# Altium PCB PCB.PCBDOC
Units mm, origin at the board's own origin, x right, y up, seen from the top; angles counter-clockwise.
Board outline 152.4 x 101.6 mm, 2 copper layers (Top Layer, Bottom Layer); 40 components, 0 nets, 156 pads, 0 vias.
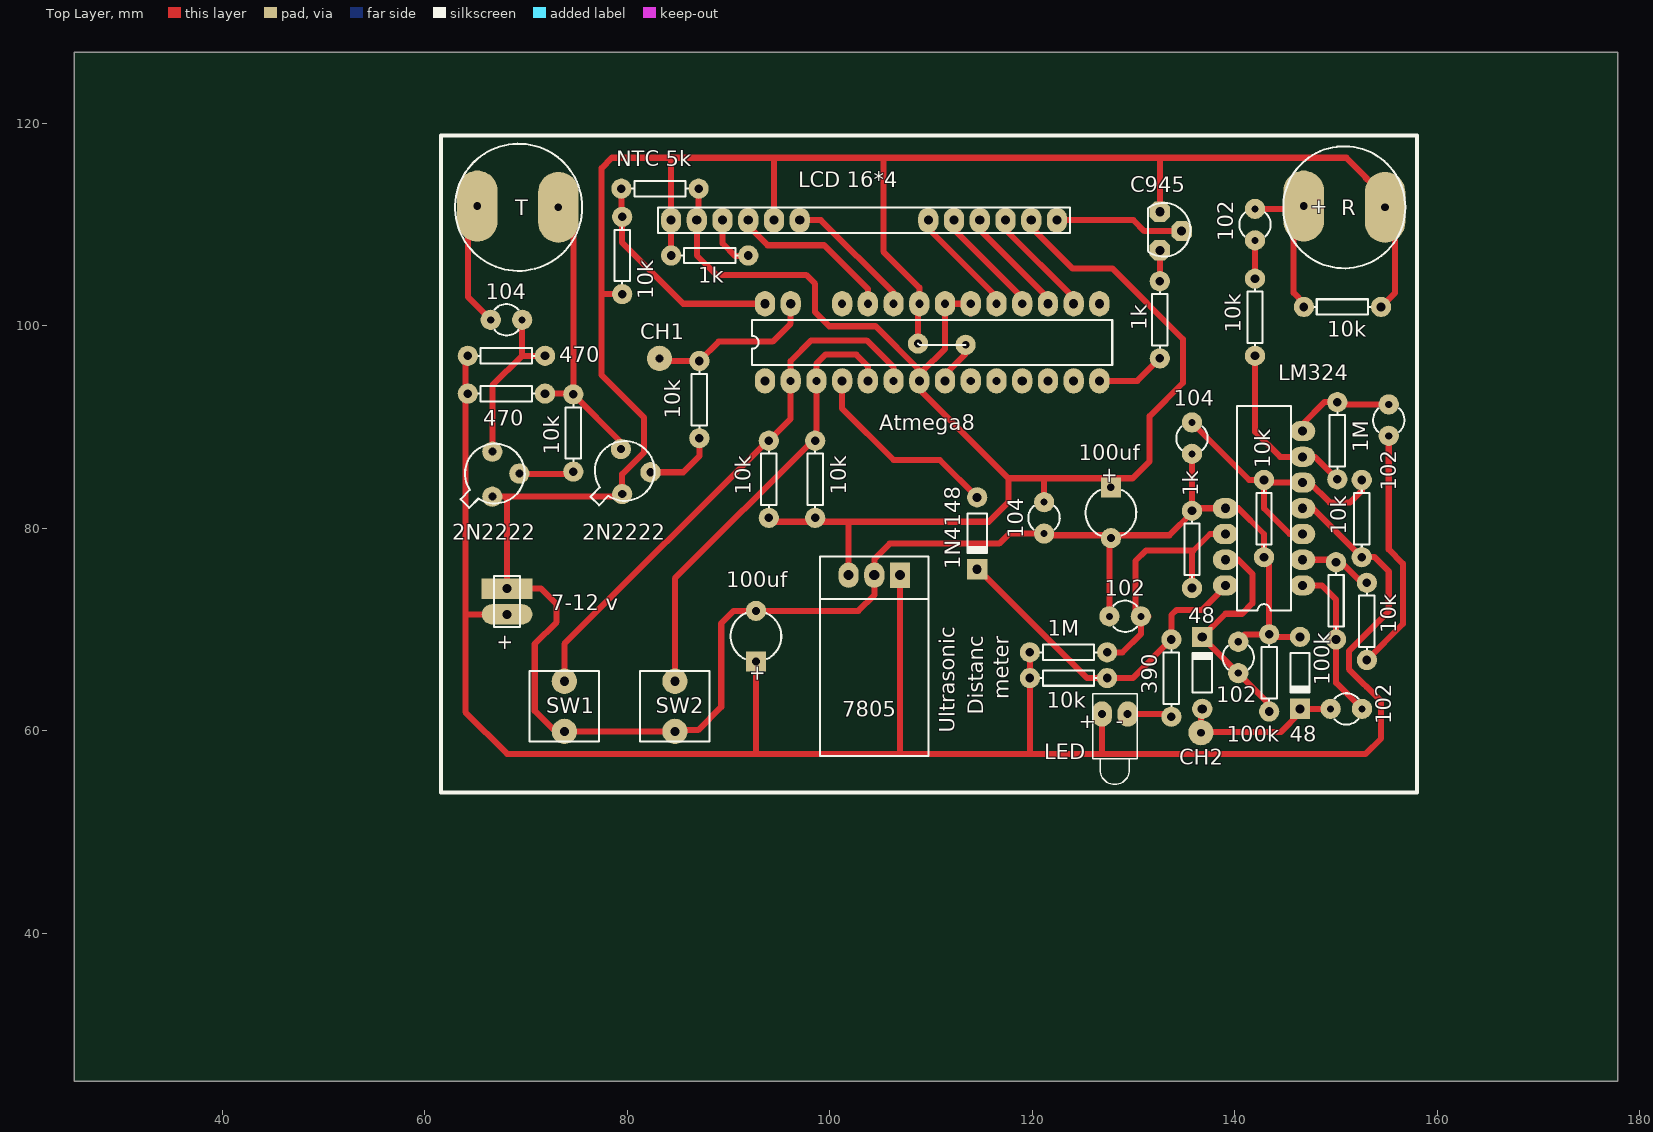
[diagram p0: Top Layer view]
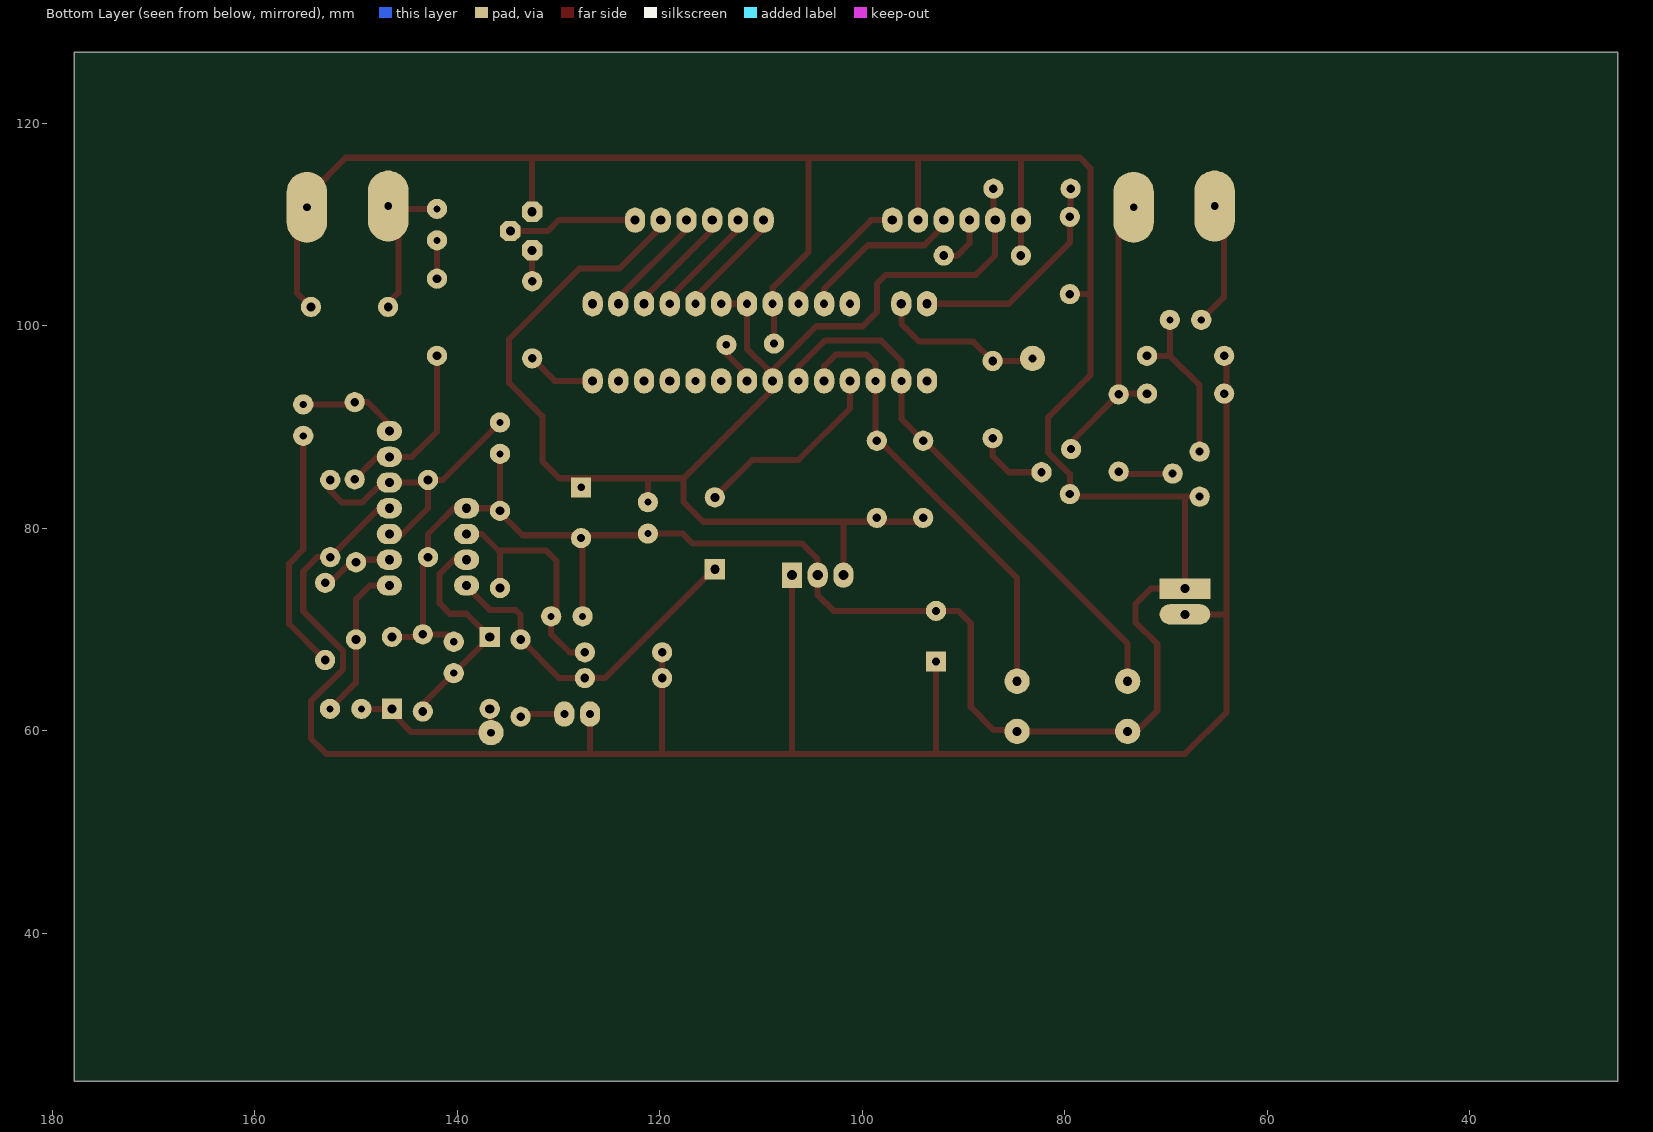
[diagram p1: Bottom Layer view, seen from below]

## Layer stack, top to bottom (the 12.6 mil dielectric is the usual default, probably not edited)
Top Layer: signal copper 0.0356
Dielectric: dielectric 0.32, FR-4, Dk 4.8
Bottom Layer: signal copper 0.0356

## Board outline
25.4,25.4 177.8,25.4 177.8,127 25.4,127

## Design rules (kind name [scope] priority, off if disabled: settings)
Clearance [All] p1: gap=0.254
ComponentClearance [All] p1: gap=0.254 collisioncheckmode=0
PolygonConnect [All] p1: connectstyle=Relief reliefconductorwidth=0.254 reliefentries=4 polygonreliefangle="90 Angle"
RoutingLayers [All] p1: top layer=Horizontal bottom layer=Vertical
RoutingVias [All] p1: holewidth=0.711 width=1.27 viastyle="Through Hole" minholewidth=0.711 minwidth=1.27 maxholewidth=0.711 maxwidth=1.27
SolderMaskExpansion [All] p1: expansion=0.102
TestPointUsage [All] p1: valid=0 allowmultiple=FALSE
Testpoint [All] p1: side=15 testpointundercomponent=TRUE minsize=1.016 maxsize=2.54 preferedsize=1.524 minholesize=0 maxholesize=1.016 preferedholesize=0.813 testpointgrid=0.025 style=1023 order=1234567890
Width [All] p1: maxlimit=0.254 minlimit=0.254 preferedwidth=0.254
16 further rules are at their usual default settings.

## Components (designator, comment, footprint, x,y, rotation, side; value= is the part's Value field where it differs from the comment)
1k "Comment" AXIAL-0.3 88.138,106.934 r180 top
1k "Comment" AXIAL-0.3 135.763,77.912 r270 top
1k "Comment" AXIAL-0.3 132.588,100.584 r270 top
1M "Comment" AXIAL-0.3 123.571,67.752 r0 top
1M "Comment" AXIAL-0.3 150.114,88.646 r270 top
1N4148 "Comment" DIO7.1-3.9x1.9 114.554,79.502 r270 top
"7-12 v" "Comment" HDR1X2 68.133,74.041 r270 top
10k "Comment" AXIAL-0.3 123.571,65.212 r0 top
10k "Comment" AXIAL-0.3 153.035,70.8 r270 top
10k "Comment" AXIAL-0.3 152.527,80.96 r270 top
10k "Comment" AXIAL-0.3 142.875,80.96 r270 top
10k "Comment" AXIAL-0.3 141.986,100.838 r270 top
10k "Comment" AXIAL-0.3 150.622,101.854 r180 top
10k "Comment" AXIAL-0.3 74.676,89.408 r270 top
10k "Comment" AXIAL-0.3 79.502,106.934 r90 top
10k "Comment" AXIAL-0.3 87.122,92.71 r270 top
10k "Comment" AXIAL-0.3 93.98,84.836 r270 top
10k "Comment" AXIAL-0.3 98.552,84.836 r270 top
48 "Comment" DIO7.1-3.9x1.9 136.779,65.72 r90 top
48 "Comment" DIO7.1-3.9x1.9 146.431,65.72 r270 top
100k "Comment" AXIAL-0.3 143.383,65.72 r270 top
100k "Comment" AXIAL-0.3 149.987,72.832 r270 top
100uf "Comment" CAPPR5-5X5 92.71,69.342 r90 top
100uf "Comment" CAPPR5-5X5 127.762,81.534 r270 top
102 "Comment" BCY-W2/D3.1 129.159,71.308 r90 top
102 "Comment" BCY-W2/D3.1 140.335,67.244 r0 top
102 "Comment" BCY-W2/D3.1 151.003,62.164 r90 top
102 "Comment" BCY-W2/D3.1 155.194,90.678 r0 top
102 "Comment" BCY-W2/D3.1 141.986,109.982 r180 top
104 "Comment" BCY-W2/D3.1 135.763,88.9 r0 top
104 "Comment" BCY-W2/D3.1 121.158,81.026 r180 top
104 "Comment" BCY-W2/D3.1 68.072,100.584 r90 top
390 "Comment" AXIAL-0.3 133.731,65.212 r270 top
470 "Comment" AXIAL-0.3 68.072,97.028 r180 top
470 "Comment" AXIAL-0.3 68.072,93.3 r180 top
Atmega8 "Comment" 28P3 110.109,98.364 r0 top
"LCD 16*4" "Comment" HDR1X16 84.328,110.424 r0 top
LED "Comment" LED-1 128.143,61.656 r270 top
LM324 "Comment" DIP-14 142.875,81.976 r90 top
"NTC 5k" "Comment" AXIAL-0.3 83.234,113.538 r0 top

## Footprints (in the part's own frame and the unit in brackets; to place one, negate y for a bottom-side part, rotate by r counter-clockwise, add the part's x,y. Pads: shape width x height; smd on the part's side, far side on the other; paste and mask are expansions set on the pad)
28P3 [mm] "DIP; 28 Leads; Row Spacing 7.62 mm; Pitch 2.54 mm"
  oval 2x2.5 hole 0.9 paste+0: 1(-16.51,-3.81) 4(-8.89,-3.81) 5(-6.35,-3.81) 7(-1.27,-3.81) 8(1.27,-3.81) 11(8.89,-3.81) 12(11.43,-3.81) 13(13.97,-3.81) 14(16.51,-3.81)
  oval 2x2.5 hole 0.8 paste+0: 2(-13.97,-3.81) 3(-11.43,-3.81) 6(-3.81,-3.81) 9(3.81,-3.81) 10(6.35,-3.81)
  oval 2x2.5 hole 0.9: 15(16.51,3.81) 16(13.97,3.81) 17(11.43,3.81) 27(-13.97,3.81) 28(-16.51,3.81)
  oval 2x2.5 hole 0.8: 18(8.89,3.81) 19(6.35,3.81) 20(3.81,3.81) 21(1.27,3.81) 22(-1.27,3.81) 23(-3.81,3.81) 24(-6.35,3.81) 25(-8.89,3.81)
  round 0 all layers, no hole: 26(-11.43,3.81)
  silkscreen extent -17.78,-2.23 17.78,2.23
AXIAL-0.3 [mm]
  round 2 hole 0.85: 1(-3.81,0) 2(3.81,0)
  silkscreen extent -2.77,-0.76 2.77,0.76
BCY-W2/D3.1 [mm]
  round 2 hole 0.7: 1(0,1.55) 2(0,-1.55)
  silkscreen extent -1.55,-1.19 1.55,1.17
CAPPR5-5X5 [mm]
  rect 2x2 hole 0.75: 1(-2.5,0)
  round 2 hole 0.8: 2(2.5,0)
  silkscreen extent -2.26,-2.5 2.27,2.5
DIO7.1-3.9x1.9 [mm]
  round 2 hole 0.9: 1(-3.55,0)
  rect 2x2 hole 0.9: 2(3.55,0)
  silkscreen extent -1.95,-0.95 2.05,0.95
DIP-14 [mm]
  oval 2x2.5 hole 0.9: 1(-7.62,-3.81) 2(-5.08,-3.81) 3(-2.54,-3.81) 4(0,-3.81) 5(2.54,-3.81) 6(5.08,-3.81) 7(7.62,-3.81) 11(0,3.81) 12(-2.54,3.81) 13(-5.08,3.81) 14(-7.62,3.81)
  round 0 all layers, no hole: 8(7.62,3.81) 9(5.08,3.81) 10(2.54,3.81)
  silkscreen extent -10.1,-2.65 10.1,2.65
HDR1X2 [mm] "Connector; Header; 2 Position"
  rect 2x5 hole 0.9: 1(0,0)
  oval 2x5 hole 0.9: 2(2.54,0)
  silkscreen extent -1.27,-1.27 3.81,1.27
HDR1X16 [mm] "Connector; Header; 16 Position"
  oval 2x2.5 hole 0.9: 1(0,0) 2(2.54,0) 3(5.08,0) 4(7.62,0) 5(10.16,0) 6(12.7,0) 11(25.4,0) 12(27.94,0) 13(30.48,0) 14(33.02,0) 15(35.56,0) 16(38.1,0)
  round 0 all layers, no hole: 7(15.24,0) 8(17.78,0) 9(20.32,0) 10(22.86,0)
  silkscreen extent -1.27,-1.27 39.37,1.27
LED-1 [mm]
  oval 2.5x2 hole 0.8: 1(0,1.27) 2(0,-1.27)
  silkscreen extent -2,-2.2 6.95,2.2

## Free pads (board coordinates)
  oval 4x7 hole 0.762: 0(65.2,111.821) 0(146.796,111.821) 1(73.2,111.694) 1(154.829,111.694)
  round 2.5 hole 0.762: 0(83.185,96.774) 1(136.652,59.817)
  round 2 hole 0.8: 1(66.675,83.119) 1(79.502,83.373) 2(69.342,85.405) 2(82.296,85.532) 3(66.675,87.564) 3(79.375,87.818)
  round 2.5 hole 0.9: 1(73.787,59.944) 1(73.787,64.897) 1(84.709,59.944) 1(84.709,64.897)
  rect 2x2.5 hole 1: 1(106.934,75.372)
  oct 2x2 hole 0.9: 1(132.588,111.252) 2(134.747,109.347) 3(132.588,107.442)
  oval 2x2.5 hole 1: 2(104.394,75.372) 3(101.854,75.372)
  round 2 hole 0.762: 10(113.411,98.11) 11(108.712,98.237)

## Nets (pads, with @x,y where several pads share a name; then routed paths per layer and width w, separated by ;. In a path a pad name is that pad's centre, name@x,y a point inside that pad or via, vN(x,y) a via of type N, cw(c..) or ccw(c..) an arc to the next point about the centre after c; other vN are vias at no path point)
pads on no net: 1k.1 1k.2 1M.1 1M.2 1N4148.1 1N4148.2 10k.1 10k.2 48.1 48.2 100k.1 100k.2 100uf.1 100uf.2 102.1 102.2 104.1 104.2 390.1 390.2 470.1 470.2 "7-12 v.1" "7-12 v.2" "LCD 16*4.1" "LCD 16*4.2" "LCD 16*4.3" "LCD 16*4.4" "LCD 16*4.5" "LCD 16*4.6" "LCD 16*4.7" "LCD 16*4.8" "LCD 16*4.9" "LCD 16*4.10" "LCD 16*4.11" "LCD 16*4.12" "LCD 16*4.13" "LCD 16*4.14" "LCD 16*4.15" "LCD 16*4.16" "NTC 5k.1" "NTC 5k.2" Atmega8.1 Atmega8.2 Atmega8.3 Atmega8.4 Atmega8.5 Atmega8.6 Atmega8.7 Atmega8.8 Atmega8.9 Atmega8.10 Atmega8.11 Atmega8.12 Atmega8.13 Atmega8.14 Atmega8.15 Atmega8.16 Atmega8.17 Atmega8.18 Atmega8.19 Atmega8.20 Atmega8.21 Atmega8.22 Atmega8.23 Atmega8.24 Atmega8.25 Atmega8.26 Atmega8.27 Atmega8.28 LED.1 LED.2 LM324.1 LM324.2 LM324.3 LM324.4 LM324.5 LM324.6 LM324.7 LM324.8 LM324.9 LM324.10 LM324.11 LM324.12 LM324.13 LM324.14
copper on no net: | length 1261.1
  Top Layer w0.4: 73.787,59.944 74.168,59.944 74.422,60.198 ; 84.709,59.944 85.09,59.944 85.344,60.198 ; 145.77,111.532 145.796,111.506
  Top Layer w0.6: 64.008,71.374 64.135,71.501 68.133,71.501 68.006,71.374 ; 64.008,75.057 64.008,96.901 ; 64.008,75.184 64.008,61.849 68.138,57.719 83.693,57.719 ; 64.135,111.694 64.262,111.821 64.262,102.844 66.522,100.584 ; 66.106,83.119 66.675,83.119 79.248,83.119 79.502,83.373 79.502,85.344 81.661,87.503 81.661,90.932 77.47,95.123 77.47,115.57 78.486,116.586 151.003,116.586 153.062,114.527 153.062,114.461 ; 66.675,87.564 66.675,94.107 69.622,97.054 ; 68.199,83.119 68.133,83.053 68.133,74.041 71.501,74.041 73.025,72.517 73.025,70.739 70.866,68.58 70.866,64.135 ; 69.088,85.344 73.914,85.344 ; 69.342,85.151 69.342,85.405 ; 69.622,100.584 69.622,97.054 ; 70.866,64.389 70.866,61.976 72.898,59.944 84.709,59.944 84.836,60.071 86.995,60.071 89.281,62.357 89.281,65.024 89.281,70.612 90.511,71.842 92.71,71.842 ; 71.882,93.3 74.594,93.3 74.676,93.218 ; 71.882,97.028 69.648,97.028 69.622,97.054 ; 73.787,64.897 73.787,68.58 93.853,88.646 93.98,88.646 96.139,90.805 96.139,94.554 ; 73.787,111.567 74.041,111.821 ; 73.914,111.313 74.168,111.567 74.295,111.694 ; 74.422,111.567 74.295,111.694 ; 77.47,103.124 79.502,103.124 ; 79.06,87.818 79.375,87.818 ; 79.424,113.538 79.424,110.822 79.502,110.744 79.502,108.204 85.532,102.174 93.599,102.174 ; 79.883,88.326 79.375,87.818 ; 82.296,85.532 85.532,85.532 87.122,87.122 87.122,88.9 ; 83.058,96.52 87.122,96.52 89.027,98.425 94.361,98.425 96.139,100.203 96.139,102.174 96.139,101.727 ; 83.312,57.719 152.908,57.719 154.432,59.243 154.432,62.926 ; 84.328,107.122 84.328,110.424 84.328,114.488 ; 84.328,113.538 84.328,116.459 84.455,116.586 ; 84.709,64.897 84.709,75.057 98.298,88.646 98.552,88.646 ; 86.868,108.138 86.868,110.678 ; 86.868,108.331 86.868,106.934 88.773,105.029 97.663,105.029 98.552,104.14 98.552,101.346 99.949,99.949 104.521,99.949 108.839,95.631 108.839,94.554 ; 86.868,110.617 87.044,110.793 87.044,113.538 ; 89.408,110.424 89.408,108.138 90.678,106.868 91.694,106.868 ; 91.948,109.601 91.948,110.424 ; 91.948,109.728 91.948,110.236 ; 92.67,71.882 92.71,71.842 ; 92.71,57.719 92.71,66.842 ; 93.853,80.645 106.68,80.645 ; 94.488,110.424 94.488,114.615 ; 94.488,113.919 94.488,116.459 94.615,116.586 ; 96.012,94.427 96.139,94.554 ; 97.028,110.424 99.126,110.424 106.299,103.251 106.299,102.174 ; 98.552,88.773 98.679,88.9 98.679,94.554 98.679,96.266 99.568,97.155 102.616,97.155 103.759,96.012 103.759,94.554 ; 101.219,94.554 101.219,92.329 101.219,91.821 106.299,86.741 110.865,86.741 114.554,83.052 ; 101.854,75.372 101.854,80.645 ; 103.759,102.174 103.759,103.632 99.441,107.95 93.853,107.95 91.948,109.855 91.948,110.424 ; 104.902,80.645 115.697,80.645 117.628,82.576 117.628,84.937 ; 105.283,116.586 105.283,107.315 108.839,103.759 108.839,102.174 108.712,102.047 108.712,98.237 ; 106.299,94.554 106.299,95.885 103.632,98.552 98.171,98.552 96.139,96.52 96.139,94.554 ; 106.934,57.912 106.934,75.372 ; 108.585,98.11 108.712,98.237 ; 108.712,97.983 108.712,98.237 ; 108.712,98.364 108.712,98.237 ; 108.839,95.189 108.839,94.554 ; 109.093,95.443 111.379,97.729 111.379,102.174 113.919,102.174 113.919,101.219 ; 109.728,110.424 109.728,109.601 116.459,102.87 116.459,102.174 ; 111.379,94.554 111.379,95.189 113.411,97.221 113.411,98.11 ; 112.268,110.424 112.268,109.474 118.999,102.743 118.999,102.174 ; 114.554,75.952 114.675,75.952 125.415,65.212 ; 114.808,110.424 114.808,109.474 121.539,102.743 121.539,102.174 ; 117.348,110.424 117.348,109.474 124.079,102.743 124.079,102.174 ; 119.761,57.719 119.761,67.752 ; 119.888,110.424 119.888,109.728 123.952,105.664 127.889,105.664 134.874,98.679 134.874,94.361 131.572,91.059 131.572,86.614 129.895,84.937 125.603,84.937 ; 120.711,79.309 123.063,79.309 ; 121.158,79.476 117.703,79.476 116.713,78.486 105.918,78.486 104.394,76.962 104.394,75.372 104.394,73.406 102.83,71.842 92.71,71.842 ; 121.158,82.576 121.158,84.81 121.285,84.937 ; 122.428,110.424 129.987,110.424 131.064,109.347 134.747,109.347 ; 122.555,79.309 128.143,79.309 ; 123.698,66.929 125.415,65.212 ; 126.619,94.554 130.368,94.554 132.588,96.774 ; 126.873,57.719 126.873,61.656 ; 127.381,67.752 128.905,67.752 130.709,69.556 130.709,71.308 131.445,71.308 ; 127.508,71.308 127.609,71.308 ; 127.635,71.054 127.635,76.769 ; 127.635,76.581 127.635,79.309 133.538,79.309 135.763,81.534 135.763,81.722 135.763,87.35 ; 127.762,84.034 126.859,84.937 117.628,84.937 ; 129.413,61.656 133.477,61.656 133.731,61.402 ; 130.175,71.181 130.175,76.769 131.23,77.824 135.929,77.824 ; 132.588,104.394 132.588,107.442 ; 132.588,111.252 132.588,116.586 ; 135.763,74.102 135.763,77.658 137.541,79.436 139.065,79.436 ; 135.763,90.45 135.763,90.424 141.417,84.77 142.875,84.77 ; 136.144,81.976 139.065,81.976 140.335,81.976 142.875,79.436 142.875,77.15 ; 136.652,59.817 136.652,61.976 ; 136.967,59.878 139.071,59.878 141.605,59.878 ; 139.065,74.356 139.065,74.229 136.779,71.943 134.239,71.943 133.731,71.435 133.731,69.022 129.921,65.212 127.381,65.212 125.415,65.212 ; 140.208,76.896 139.065,76.896 140.335,76.896 141.732,75.499 141.732,72.578 140.716,71.562 139.071,71.562 136.779,69.27 136.779,69.25 143.383,62.646 143.383,61.91 143.123,62.17 ; 140.335,68.641 140.335,69.27 ; 140.335,68.794 140.335,68.895 140.97,69.53 143.383,69.53 ; 141.351,59.878 144.526,59.878 146.431,61.783 146.431,62.17 149.447,62.17 149.453,62.164 ; 141.986,94.107 141.986,97.028 ; 141.986,94.488 141.986,89.535 144.465,87.056 146.685,87.056 146.939,87.31 ; 141.986,104.648 141.986,108.432 ; 141.986,111.532 145.643,111.532 145.796,111.379 ; 142.875,77.023 142.875,77.15 ; 145.669,111.948 145.796,111.821 145.796,103.251 146.812,102.235 146.812,101.854 ; 146.431,69.27 143.643,69.27 143.383,69.53 ; 146.558,87.056 147.894,87.056 150.114,84.836 ; 146.685,74.356 148.59,74.356 149.987,72.959 149.987,68.768 ; 146.685,76.896 149.733,76.896 149.987,76.642 150.495,76.642 152.527,74.61 153.162,74.61 ; 146.685,79.436 145.415,79.436 142.875,81.976 142.875,84.77 ; 146.685,81.976 147.701,81.976 152.527,77.15 153.797,77.15 155.194,75.753 155.194,71.816 151.257,67.879 151.257,66.101 154.432,62.926 ; 146.685,89.596 146.685,90.297 148.844,92.456 150.495,92.456 150.723,92.228 155.194,92.228 ; 149.987,69.022 149.987,66.101 149.987,64.73 152.553,62.164 ; 152.527,84.77 152.527,83.693 151.384,82.55 149.352,82.55 147.386,84.516 146.685,84.516 143.129,84.516 142.875,84.77 ; 152.908,114.615 155.829,111.694 ; 153.009,64.349 154.432,62.926 ; 153.035,66.99 156.591,70.546 156.591,76.515 155.194,77.912 155.194,78.166 155.194,89.128 ; 154.432,101.854 155.829,103.251 155.829,111.694 ; 155.194,112.329 155.829,111.694 ; 74.295,111.694 74.676,111.313 74.676,93.218 ; 74.676,93.218 79.375,88.519 79.375,87.818 ; 91.948,110.424 91.948,109.916 91.948,110.424 ; 108.839,94.554 108.839,93.726 117.628,84.937 ; 142.875,77.15 142.875,76.896 143.383,76.388 143.383,69.53
  Top Layer w0.8: 73.66,65.024 73.787,64.897 ; 73.787,59.69 73.787,59.944 ; 84.582,65.024 84.709,64.897 ; 84.709,59.69 84.709,59.944

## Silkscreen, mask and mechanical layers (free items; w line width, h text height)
Top Overlay:
  circle w0.2: c150.803,111.694 r6.024
  circle w0.2: c69.269,111.694 r6.277
  lines w0.2: 99.044,73.022 109.744,73.022 ; 108.712,98.237 108.839,98.11 113.411,98.11 ; 131.419,107.374 131.419,111.574 ; 131.449,107.303 ccw(c132.969,109.474) 131.449,111.645 ; 63.543,82.868 64.392,82.019 65.311,82.938 ccw(c66.929,85.405) 64.462,83.787 63.543,82.868 ; 70.358,58.928 77.216,58.928 77.216,65.913 70.358,65.913 70.358,58.928 ; 76.37,83.122 77.219,82.273 78.138,83.192 ccw(c79.756,85.659) 77.289,84.041 76.37,83.122 ; 81.28,58.928 88.138,58.928 88.138,65.913 81.28,65.913 81.28,58.928 ; 99.044,57.536 99.044,77.222 109.744,77.222 109.744,57.536 99.044,57.536
  lines w0.4: 127,53.909 157.988,53.909 157.988,118.806 61.595,118.806 61.595,53.909 127.254,53.909
  text "C945" at 129.667,113.157 h1.5
  text "+" at 147.447,111.125 h1.52
  text "T" at 68.961,110.932 h1.52
  text "R" at 150.495,110.932 h1.52
  text "CH1" at 81.28,98.679 h1.52
  text "2N2222" at 62.738,78.867 h1.52
  text "2N2222" at 75.565,78.867 h1.52
  text "+" at 67.31,69.596 h1.52 r270
  text "meter" at 117.668,63.119 h1.52 r90
  text "SW1" at 72.009,61.722 h1.52
  text "SW2" at 82.804,61.722 h1.52
  text "Distanc" at 115.128,61.595 h1.52 r90
  text "7805" at 101.219,61.402 h1.52
  text "+   -" at 124.587,60.259 h1.52
  text "Ultrasonic" at 112.334,59.817 h1.52 r90
  text "CH2" at 134.493,56.642 h1.52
